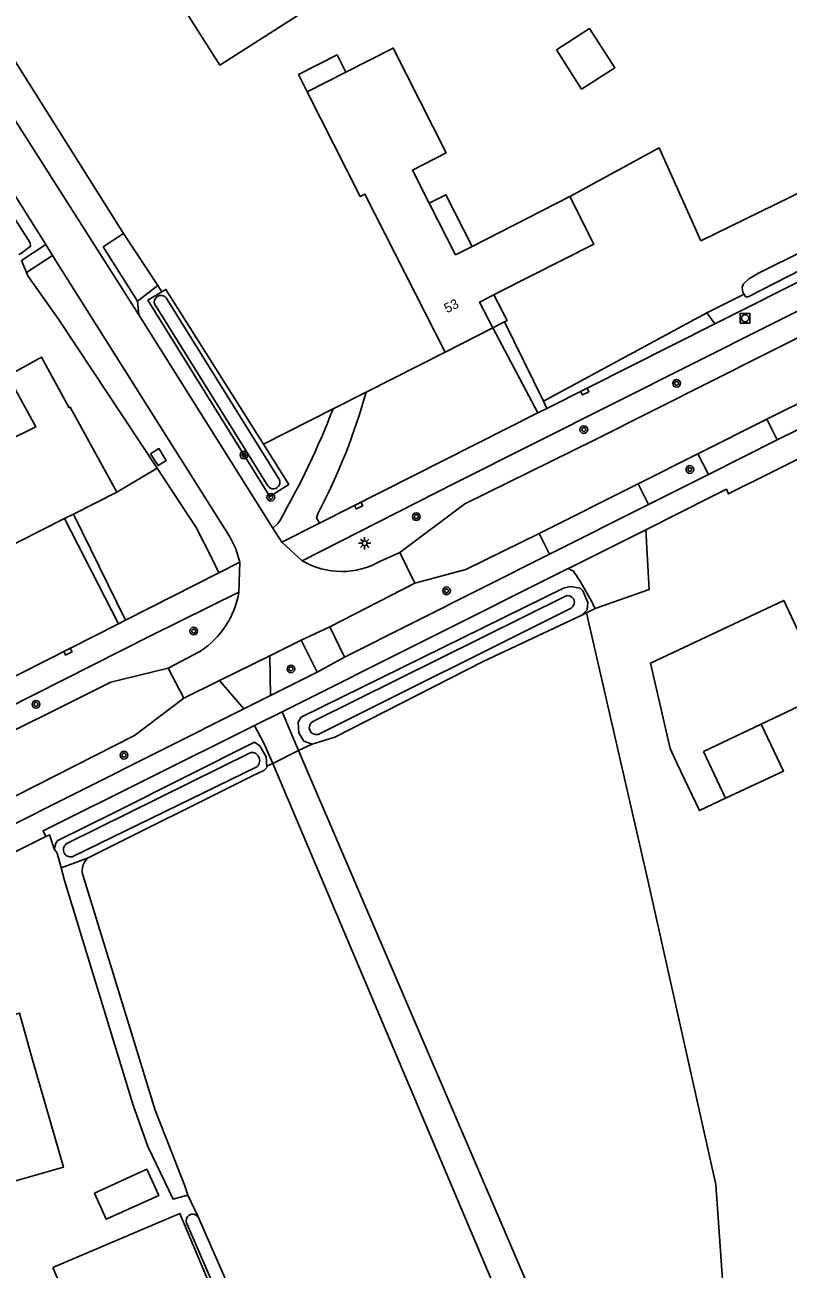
# Model space of a CAD drawing. Extents: x 140000 to 143000, y 403500 to 406000.
# Drawn here: x 141024.3 to 141103.5, y 404792.3 to 404921.3 of the extents above; entities that cross this region are included whole.
import ezdxf

# ---------------------------------------------------------------- set-up
doc = ezdxf.new("R2010")
doc.units = 0
for name, color, linetype in [('gg-afsc-erfafscheiding', 7, 'Continuous'), ('gg-afsc-hekwerk', 7, 'Continuous'), ('gg-anno-huisnummerreeks BGT', 7, 'Continuous'), ('gg-bbg-bassin', 7, 'Continuous'), ('gg-bbg-bijgebouw', 7, 'Continuous'), ('gg-bbg-gedigitaliseerde bijgebouw', 7, 'Continuous'), ('gg-bbg-hoofdgebouw', 7, 'Continuous'), ('gg-bbg-luifel en loopbrug', 7, 'Continuous'), ('gg-bbg-overig bouwwerk', 7, 'Continuous'), ('gg-knt-verharding', 7, 'Continuous'), ('gg-knt-verharding nz', 7, 'Continuous'), ('gg-kntw-bovenkant insteek waterloop', 7, 'Continuous'), ('gg-kntw-waterlijn', 7, 'Continuous'), ('gt-grn-groengrens', 7, 'Continuous'), ('gt-grn-groengrens NZ', 7, 'Continuous'), ('gt-grn-weggrens', 7, 'Continuous'), ('gt-symb-boom', 7, 'Continuous'), ('gt-symb-kolk', 7, 'Continuous'), ('gt-symb-lichtmast', 7, 'Continuous'), ('gt-symb-rioolschacht', 7, 'Continuous')]:
    doc.layers.add(name, color=color, linetype=linetype)

# ---------------------------------------------------------------- blocks, each defined once
blk = doc.blocks.new('gt0-BOOM')
at = {"layer": 'gt-symb-boom'}
for radius in [0.4, 0.2]:
    blk.add_circle((0, 0), radius, dxfattribs=at)
blk = doc.blocks.new('gt0-KOLK')
at = {"layer": 'gt-symb-kolk'}
blk.add_lwpolyline([(0, 0), (0.38, 0), (0.38, 0.4), (-0.37, 0.4), (-0.37, 0), (0, 0)], dxfattribs=at)
blk = doc.blocks.new('gt0-RS')
at = {"layer": 'gt-symb-rioolschacht'}
blk.add_lwpolyline([(-0.5, -0.5), (0.5, -0.5), (0.5, 0.5), (-0.5, 0.5)], close=True, dxfattribs=at)
blk.add_circle((0, 0), 0.375, dxfattribs=at)
blk = doc.blocks.new('gt0-LMAST')
at = {"layer": 'gt-symb-lichtmast'}
for p, q in [((-0.18, 0.17), (-0.45, 0.44)), ((-0.01, 0.25), (-0.01, 0.62)), ((0.17, 0.17), (0.44, 0.44)), ((-0.26, 0), (-0.63, 0)), ((-0.18, -0.18), (-0.45, -0.45)), ((-0.01, -0.25), (-0.01, -0.63)), ((0.44, -0.45), (0.17, -0.18)), ((0.24, 0), (0.62, 0))]:
    blk.add_line(p, q, dxfattribs=at)
blk.add_circle((-0.01, 0), 0.25, dxfattribs=at)

msp = doc.modelspace()

# ---------------------------------------------------------------- linework, layer by layer
at = {"layer": 'gg-afsc-erfafscheiding'}
for p, q in [((141008.04, 404941.68), (141034.56, 404899.71)), ((141038.12, 404894.31), (141038.52, 404893.65)), ((141033.85, 404872.86), (141038.02, 404875.36)), ((141034.75, 404859.59), (141029.37, 404870.6)), ((141034.03, 404859.22), (141028.43, 404870.13)), ((141083.48, 404860.79), (141082.57, 404860.35))]:
    msp.add_line(p, q, dxfattribs=at)
for points in [[(141053.95, 404966.24), (141025.15, 404947.73), (141044.55, 404917.17), (141073.64, 404935.77), (141053.95, 404966.24)], [(141080.85, 404903.54), (141090.13, 404908.58), (141094.44, 404898.95), (141112.96, 404907.99), (141113.42, 404907.16), (141115.01, 404907.97)], [(141038.02, 404875.36), (141027.8, 404890.82), (141024.63, 404895.32), (141024.49, 404895.65)], [(141044.44, 404864.49), (141043.78, 404865.87), (141042.09, 404869.2), (141038.02, 404875.36)], [(141026.47, 404837.15), (141026.88, 404837.34), (141027.36, 404835.89)]]:
    msp.add_lwpolyline(points, dxfattribs=at)
at = {"layer": 'gg-afsc-hekwerk'}
msp.add_line((141027.8, 404890.82), (141024.63, 404895.32), dxfattribs=at)
msp.add_lwpolyline([(141044.55, 404917.17), (141073.64, 404935.77), (141053.95, 404966.24), (141025.15, 404947.73), (141044.55, 404917.17)], dxfattribs=at)
at = {"layer": 'gg-bbg-bassin'}
msp.add_lwpolyline([(141037.36, 404876.85), (141038.2, 404877.39), (141038.98, 404876.16), (141038.13, 404875.63), (141037.36, 404876.85)], dxfattribs=at)
at = {"layer": 'gg-bbg-bijgebouw'}
msp.add_line((141100.71, 404848.82), (141094.71, 404845.99), dxfattribs=at)
for points in [[(141091.99, 404844.71), (141091.25, 404846.29), (141089.23, 404855.13), (141103.05, 404861.65), (141107.56, 404852.06), (141100.71, 404848.82)], [(141027.22, 404792.47), (141045.86, 404748.5), (141058.93, 404754.05), (141040.39, 404798.07), (141027.22, 404792.47)]]:
    msp.add_lwpolyline(points, dxfattribs=at)
at = {"layer": 'gg-bbg-gedigitaliseerde bijgebouw'}
msp.add_line((141094.71, 404845.99), (141097.01, 404841.12), dxfattribs=at)
for points in [[(141079.45, 404918.73), (141082.07, 404914.67), (141085.52, 404916.89), (141082.9, 404920.95), (141079.45, 404918.73)], [(141097.01, 404841.12), (141094.29, 404839.84), (141091.99, 404844.71)]]:
    msp.add_lwpolyline(points, dxfattribs=at)
at = {"layer": 'gg-bbg-hoofdgebouw'}
for p, q in [((141057.6, 404916.44), (141053.59, 404914.4)), ((141080.85, 404903.54), (141070.71, 404898.36)), ((141072.87, 404889.91), (141067.9, 404887.38)), ((141029.37, 404870.6), (141033.85, 404872.86)), ((141029.37, 404870.6), (141028.43, 404870.13)), ((141010.81, 404861.24), (141028.43, 404870.13))]:
    msp.add_line(p, q, dxfattribs=at)
for points in [[(141066.27, 404902.83), (141064.51, 404906.28), (141068.03, 404908.07), (141062.52, 404918.93), (141057.6, 404916.44)], [(141067.9, 404887.38), (141059.58, 404903.78), (141059.1, 404903.54), (141053.59, 404914.4)], [(141070.71, 404898.36), (141068.99, 404897.49), (141066.27, 404902.83)], [(141072.96, 404893.34), (141073.42, 404893.57), (141083.35, 404898.6), (141080.85, 404903.54)], [(141072.87, 404889.91), (141071.49, 404892.59), (141072.96, 404893.34)], [(141033.85, 404872.86), (141029.01, 404881.67), (141028.92, 404881.62), (141026.04, 404886.86), (141022.55, 404884.94), (141025.45, 404879.66), (141006.29, 404870.21), (141010.81, 404861.24)], [(141022.36, 404818.44), (141020.4, 404825.27), (141012.22, 404822.92), (141012.85, 404820.7), (141011.47, 404820.31), (141012.88, 404815.51), (141017.4, 404799.74), (141028.31, 404802.86), (141025.09, 404814.01), (141023.77, 404818.85), (141022.36, 404818.44)]]:
    msp.add_lwpolyline(points, dxfattribs=at)
at = {"layer": 'gg-bbg-luifel en loopbrug'}
msp.add_line((141074.08, 404890.53), (141072.87, 404889.91), dxfattribs=at)
for points in [[(141057.6, 404916.44), (141056.7, 404918.22), (141052.69, 404916.18), (141053.59, 404914.4)], [(141070.71, 404898.36), (141067.98, 404903.71), (141066.27, 404902.83)], [(141074.08, 404890.53), (141074.34, 404890.66), (141072.96, 404893.34)], [(141100.71, 404848.82), (141103.01, 404843.95), (141097.01, 404841.12)]]:
    msp.add_lwpolyline(points, dxfattribs=at)
at = {"layer": 'gg-bbg-overig bouwwerk'}
msp.add_lwpolyline([(141031.52, 404800.16), (141032.76, 404797.46), (141038.2, 404799.94), (141036.97, 404802.65), (141031.52, 404800.16)], dxfattribs=at)
at = {"layer": 'gg-knt-verharding'}
for p, q in [((141004.07, 404941.58), (141036.15, 404891.25)), ((141000.7, 404939.45), (141026.47, 404898.56)), ((141153.57, 404906.68), (141101.3, 404880.43)), ((141154.67, 404904.51), (141102.37, 404878.28)), ((141117.99, 404901.45), (141095.89, 404890.32)), ((141034.56, 404899.71), (141038.12, 404894.31)), ((141023.96, 404896.88), (141026.47, 404898.56)), ((141027.19, 404897.42), (141024.49, 404895.65)), ((141027.19, 404897.42), (141026.47, 404898.56)), ((141024.49, 404895.65), (141023.96, 404896.88)), ((141035.98, 404892.68), (141038.12, 404894.31)), ((141036.15, 404891.25), (141050.04, 404869.15)), ((141072.87, 404889.91), (141077.54, 404881.08)), ((141078.1, 404882.32), (141074.08, 404890.53)), ((141078.47, 404881.55), (141095.89, 404890.32)), ((141059.73, 404883.25), (141056.3, 404881.52)), ((141078.47, 404881.55), (141078.1, 404882.32)), ((141077.54, 404881.08), (141054.87, 404869.65)), ((141078.47, 404881.55), (141077.54, 404881.08)), ((141094.14, 404876.85), (141101.3, 404880.43)), ((141101.3, 404880.43), (141102.37, 404878.28)), ((141102.37, 404878.28), (141095.22, 404874.69)), ((141087.94, 404873.73), (141094.14, 404876.85)), ((141095.22, 404874.69), (141094.14, 404876.85)), ((141089.02, 404871.58), (141095.22, 404874.69)), ((141077.66, 404868.59), (141087.94, 404873.73)), ((141087.94, 404873.73), (141089.02, 404871.58)), ((141078.74, 404866.43), (141089.02, 404871.58)), ((141050.96, 404867.69), (141050.04, 404869.15)), ((141054.87, 404869.65), (141050.96, 404867.69)), ((141077.66, 404868.59), (141078.74, 404866.43)), ((141050.96, 404867.69), (141053.07, 404865.75)), ((141063.22, 404866.6), (141061.21, 404865.71)), ((141046.62, 404865.6), (141044.44, 404864.49)), ((141046.52, 404862.5), (141046.62, 404865.6)), ((141057.46, 404855.75), (141078.74, 404866.43)), ((141044.44, 404864.49), (141034.75, 404859.59)), ((141051.01, 404850.07), (141080.69, 404864.94)), ((141080.69, 404864.94), (141081.22, 404864.68)), ((141055.95, 404858.89), (141064.77, 404863.44)), ((141034.03, 404859.22), (141015.68, 404849.92)), ((141034.75, 404859.59), (141034.03, 404859.22)), ((141055.95, 404858.89), (141057.46, 404855.75)), ((141049.74, 404855.91), (141052.99, 404857.51)), ((141052.99, 404857.51), (141054.62, 404854.2)), ((141039.18, 404854.6), (141042.52, 404856.38)), ((141049.81, 404851.79), (141049.74, 404855.91)), ((141054.62, 404854.2), (141057.46, 404855.75)), ((141049.81, 404851.79), (141054.62, 404854.2)), ((141040.79, 404851.5), (141044.5, 404853.33)), ((141044.5, 404853.33), (141047.02, 404850.39)), ((141047.02, 404850.39), (141049.81, 404851.79)), ((141047.02, 404850.39), (141003.24, 404828.43)), ((141048.15, 404848.66), (141051.01, 404850.07)), ((141050.03, 404844.73), (141052.71, 404846.07)), ((141042.28, 404797.7), (141041.22, 404799.97))]:
    msp.add_line(p, q, dxfattribs=at)
for points in [[(141035.98, 404892.68), (141032.44, 404898.3), (141034.56, 404899.71)], [(141150.3, 404899.9), (141148.34, 404898.92), (141148.61, 404898.29), (141115.54, 404881.79), (141114.68, 404881.36), (141101.25, 404874.66), (141097.77, 404872.93), (141097.3, 404872.69), (141097.1, 404873.17), (141095.65, 404872.44), (141088.72, 404868.96)], [(141046.62, 404865.6), (141046.2, 404867), (141045.57, 404868.25), (141027.19, 404897.42)], [(141053.07, 404865.75), (141068.93, 404873.8), (141118.08, 404898.5)], [(141119.2, 404896.28), (141083.44, 404878.28), (141069.94, 404871.67), (141063.22, 404866.6)], [(141054.87, 404869.65), (141054.58, 404870.2), (141054.74, 404870.71)], [(141050.04, 404869.15), (141050.54, 404869.61), (141050.76, 404869.89)], [(141077.66, 404868.59), (141070.05, 404864.84), (141064.77, 404863.44)], [(141080.69, 404864.94), (141081.13, 404865.16), (141087.71, 404868.46), (141088.72, 404868.96)], [(141088.72, 404868.96), (141089.08, 404862.78), (141083.48, 404860.79)], [(141016.24, 404847.33), (141037.35, 404857.98), (141046.52, 404862.5)], [(141082.57, 404860.35), (141088.94, 404832.64), (141095.99, 404801.07), (141097.85, 404774.46), (141096.85, 404772.37), (141091.87, 404768.53)], [(141018.01, 404845.58), (141033.23, 404853.16), (141039.18, 404854.6)], [(141002.21, 404830.77), (141021.29, 404840.33), (141035.69, 404847.65), (141040.79, 404851.5)], [(141051.01, 404850.07), (141052.02, 404847.7), (141052.71, 404846.07)], [(141026.47, 404837.15), (141026.2, 404837.75), (141048.15, 404848.66)], [(141048.15, 404848.66), (141049.08, 404846.91), (141049.27, 404846.47), (141050.03, 404844.73)], [(141091.87, 404768.53), (141086.62, 404767.03), (141052.71, 404846.07)], [(141050.03, 404844.73), (141083.4, 404765.94), (141060.98, 404755.27)], [(140912.41, 404779.39), (140912.97, 404779.71), (140913.21, 404779.18), (140930.77, 404788.76), (140938.49, 404792.8), (140943.49, 404795.42), (140947.69, 404797.61), (140954.54, 404801.09), (140956.67, 404802.18), (140959.31, 404803.5), (140996.81, 404822.29), (141003.91, 404825.85), (141026.47, 404837.15)]]:
    msp.add_lwpolyline(points, dxfattribs=at)
for centre, radius, start, end in [((140997.74, 404900.64), 64.38, 332.2919, 344.3275), ((140974.77, 404913.27), 87.49, 330.2782, 338.7236), ((141057.17, 404872.73), 8.09, 239.5521, 299.9553), ((141057.04, 404848.04), 29.35, 25.757, 34.545), ((141037.47, 404864.04), 9.18, 303.4132, 350.367)]:
    msp.add_arc(centre, radius, start, end, dxfattribs=at)
at = {"layer": 'gg-knt-verharding nz'}
for p, q in [((141055.95, 404858.89), (141052.99, 404857.51)), ((141044.5, 404853.33), (141049.74, 404855.91))]:
    msp.add_line(p, q, dxfattribs=at)
at = {"layer": 'gg-kntw-bovenkant insteek waterloop'}
for p, q in [((141041.07, 404797.08), (141059.08, 404755.58)), ((141060.6, 404756.16), (141042.28, 404797.7))]:
    msp.add_line(p, q, dxfattribs=at)
for points in [[(140975.14, 404977.19), (140992.67, 404949.76), (141006.99, 404926.69), (141024.87, 404898.72), (141024.9, 404898.37), (141023.96, 404897.66), (141023.68, 404897.52)], [(141115.2, 404901.92), (141115.03, 404902.24), (141114.63, 404902.49), (141114.43, 404902.54), (141100.42, 404895.59), (141099.43, 404895), (141098.87, 404894.47), (141098.72, 404894.13), (141098.81, 404893.59), (141098.93, 404893.39)], [(141115.2, 404901.92), (141115.22, 404901.61), (141115.02, 404901.25), (141114.68, 404900.98), (141099.36, 404893.12), (141099.08, 404893.14), (141098.93, 404893.39)], [(141038.52, 404893.65), (141037.06, 404892.78), (141049.73, 404872.42), (141051.68, 404873.67), (141049.05, 404877.86)], [(141038.52, 404893.65), (141038.95, 404893.9), (141049.05, 404877.86)], [(141082.09, 404860.12), (141082.63, 404860.67), (141082.7, 404861.44), (141082.19, 404862.64), (141081.92, 404862.91), (141080.88, 404863.09), (141080.18, 404862.93), (141052.98, 404849.54), (141052.67, 404849), (141052.75, 404847.92), (141053.26, 404847.03), (141054.11, 404846.73)], [(141082.09, 404860.12), (141071.86, 404855.32), (141056.47, 404847.47), (141054.11, 404846.73)], [(141027.36, 404835.89), (141027.55, 404836.55), (141027.74, 404836.74), (141033.61, 404839.63), (141048.15, 404846.93), (141048.7, 404846.55), (141049.36, 404845.43), (141049.43, 404844.45)], [(141030.88, 404834.94), (141047.94, 404843.45), (141049.1, 404843.99), (141049.44, 404844.34), (141049.43, 404844.45)], [(141028.08, 404833.9), (141027.67, 404835.42), (141027.36, 404835.89)], [(141028.08, 404833.9), (141028.42, 404832.61), (141035.55, 404809.3), (141037.08, 404805.01), (141039.68, 404799.54), (141040.55, 404799.79), (141041.22, 404799.97)], [(141041.22, 404799.97), (141040.92, 404800.92), (141037.82, 404808.79), (141030.31, 404833.19)]]:
    msp.add_lwpolyline(points, dxfattribs=at)
for centre, radius, start, end in [((141031.93, 404833.62), 1.68, 128.5567, 194.9086), ((141041.72, 404797.3), 0.686, 121.9366, 199.161), ((141041.72, 404797.3), 0.688, 35.5385, 121.9371)]:
    msp.add_arc(centre, radius, start, end, dxfattribs=at)
at = {"layer": 'gg-kntw-waterlijn'}
for p, q in [((141050.63, 404874.33), (141038.96, 404893.03)), ((141049.53, 404873.53), (141037.92, 404892.11)), ((141080.48, 404862.13), (141054.19, 404849.1)), ((141054.74, 404847.75), (141081, 404860.85)), ((141047.74, 404845.87), (141028.73, 404836.46))]:
    msp.add_line(p, q, dxfattribs=at)
for points in [[(141029.25, 404835.05), (141029.3, 404835.08), (141048.29, 404844.34)], [(141028.08, 404833.9), (141029.48, 404834.42), (141030.88, 404834.94)]]:
    msp.add_lwpolyline(points, dxfattribs=at)
for centre, radius, start, end in [((141038.43, 404892.58), 0.694, 39.9115, 223.1361), ((141050.1, 404873.9), 0.68, 212.9066, 39.0118), ((141080.62, 404861.44), 0.704, 1.6308, 101.8939), ((141080.62, 404861.44), 0.705, 302.4769, 1.6687), ((141054.55, 404848.46), 0.733, 119.2886, 285.4845), ((141047.84, 404845.04), 0.836, 303.3055, 96.5283), ((141029.07, 404835.79), 0.755, 116.8027, 284.0054)]:
    msp.add_arc(centre, radius, start, end, dxfattribs=at)
at = {"layer": 'gt-grn-groengrens'}
for p, q in [((141098.93, 404893.39), (141095.07, 404891.48)), ((141078.1, 404882.32), (141095.07, 404891.48)), ((141067.9, 404887.38), (141059.73, 404883.25)), ((141049.05, 404877.86), (141056.3, 404881.52)), ((141082.57, 404860.35), (141082.09, 404860.12)), ((141054.11, 404846.73), (141052.71, 404846.07)), ((141049.43, 404844.45), (141050.03, 404844.73))]:
    msp.add_line(p, q, dxfattribs=at)
at = {"layer": 'gt-grn-groengrens NZ'}
msp.add_line((141035.98, 404892.68), (141036.15, 404891.25), dxfattribs=at)
at = {"layer": 'gt-grn-weggrens'}
for p, q in [((141095.89, 404890.32), (141095.07, 404891.48)), ((141063.22, 404866.6), (141064.77, 404863.44)), ((141039.18, 404854.6), (141040.79, 404851.5))]:
    msp.add_line(p, q, dxfattribs=at)

# ---------------------------------------------------------------- block references
at = {"layer": 'gt-symb-boom'}
for p in [(141091.92, 404884.16), (141082.3, 404879.36), (141047.05, 404876.73), (141093.3, 404875.22), (141049.83, 404872.34), (141064.92, 404870.33), (141068.06, 404862.64), (141041.83, 404858.46), (141051.91, 404854.54), (141025.46, 404850.87), (141034.59, 404845.59)]:
    msp.add_blockref('gt0-BOOM', p, dxfattribs=at)
at = {"layer": 'gt-symb-kolk'}
for p, rotation in [((141082.31, 404883.48), -153.2653284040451), ((141058.85, 404871.66), -153.26532840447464), ((141028.69, 404856.51), -153.12817120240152)]:
    msp.add_blockref('gt0-KOLK', p, dxfattribs=dict(at, rotation=rotation))
at = {"layer": 'gt-symb-lichtmast'}
msp.add_blockref('gt0-LMAST', (141059.57, 404867.57), dxfattribs=at)
at = {"layer": 'gt-symb-rioolschacht'}
msp.add_blockref('gt0-RS', (141099.03, 404890.9), dxfattribs=at)

# ---------------------------------------------------------------- texts
at = {"layer": 'gg-anno-huisnummerreeks BGT'}
msp.add_text('53', height=1, rotation=27, dxfattribs=at).set_placement((141068.11, 404891.41))

doc.saveas('drawing.dxf')
